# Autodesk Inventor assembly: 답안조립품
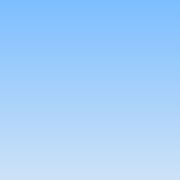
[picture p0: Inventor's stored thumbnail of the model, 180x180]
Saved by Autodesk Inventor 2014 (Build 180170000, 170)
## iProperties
Created: 2015-09
Part Number: 답안조립품
Document SubType Name: Assembly
Designer: 29
Author: 29
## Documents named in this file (1)
- C:\Users\29\Desktop\450907V1007\답안조립품.iam
